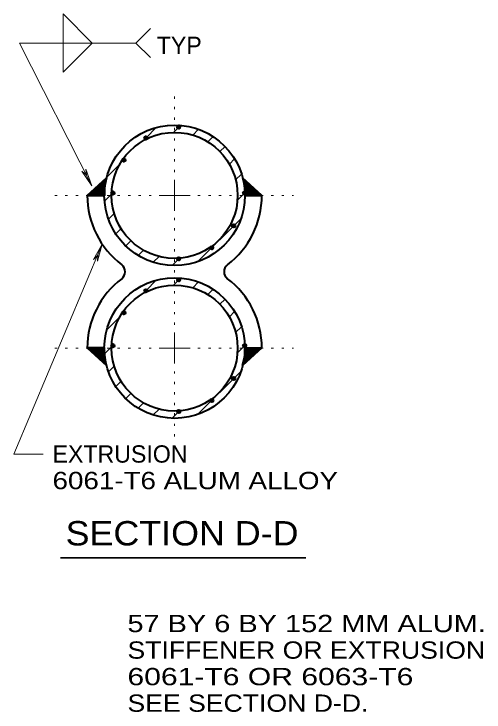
# Model space of a CAD drawing. Extents: x 312583 to 312854, y 144419 to 144597.
# Drawn here: x 312758.58 to 312779.22, y 144486.6 to 144517.27 of the extents above; entities that cross this region are included whole.
import ezdxf
from ezdxf.enums import TextEntityAlignment as Align

# ---------------------------------------------------------------- set-up
doc = ezdxf.new("R2010")
doc.units = 0
doc.header["$LTSCALE"] = 0.3
doc.header["$PDMODE"] = 32
doc.header["$PDSIZE"] = 0.15
doc.linetypes.add('DOTTED', pattern=[1.5, 0.3, -1.2])
doc.layers.add('1', color=7, linetype='Continuous', lineweight=40)

msp = doc.modelspace()

# ---------------------------------------------------------------- linework, layer by layer
at = {"layer": '1', "lineweight": 13}
for p, q in [((312761.9944, 144509.7243), (312758.8204, 144515.988)), ((312763.9341, 144515.988), (312764.5704, 144515.3516)), ((312765.5824, 144512.0626), (312765.8891, 144512.3693)), ((312764.3788, 144511.825), (312764.8234, 144512.2773)), ((312766.4258, 144511.9476), (312766.6788, 144512.2006)), ((312767.0928, 144511.6486), (312767.3228, 144511.8786)), ((312768.0358, 144510.6673), (312768.2658, 144510.8973)), ((312762.6538, 144510.1), (312763.2134, 144510.6596)), ((312761.5574, 144510.3683), (312761.7568, 144510.192)), ((312761.9944, 144509.7243), (312761.5574, 144510.3683)), ((312761.7261, 144510.4526), (312761.7568, 144510.192)), ((312761.9944, 144509.7243), (312761.7261, 144510.4526)), ((312768.3118, 144509.9773), (312768.5724, 144510.2303)), ((312765.6284, 144509.295), (312765.6284, 144509.9773)), ((312762.5541, 144509.042), (312762.8608, 144509.3486)), ((312765.6284, 144509.295), (312764.9461, 144509.295)), ((312765.6284, 144509.295), (312766.3108, 144509.295)), ((312765.6284, 144509.295), (312765.6284, 144508.6126)), ((312768.3884, 144509.088), (312768.7104, 144509.41)), ((312762.7304, 144508.2523), (312762.9758, 144508.4976)), ((312766.6558, 144506.3893), (312768.5418, 144508.2676)), ((312763.0524, 144507.6083), (312763.2824, 144507.8383)), ((312758.5751, 144497.9253), (312762.4544, 144507.1483)), ((312762.4544, 144507.1483), (312762.0711, 144506.4736)), ((312762.4544, 144507.1483), (312762.2474, 144506.4046)), ((312764.0338, 144506.6576), (312764.2638, 144506.8876)), ((312762.0711, 144506.4736), (312762.2551, 144506.6653)), ((312762.2474, 144506.4046), (312762.2551, 144506.6653)), ((312764.6931, 144506.3586), (312764.9538, 144506.6116)), ((312765.5211, 144506.213), (312765.8431, 144506.535)), ((312765.5824, 144505.3543), (312765.8891, 144505.661)), ((312764.3788, 144505.1166), (312764.8234, 144505.569)), ((312766.4258, 144505.2393), (312766.6788, 144505.4923)), ((312767.0928, 144504.9403), (312767.3228, 144505.1703)), ((312768.0358, 144503.959), (312768.2658, 144504.189)), ((312762.6538, 144503.3916), (312763.2134, 144503.9513)), ((312768.3118, 144503.269), (312768.5724, 144503.522)), ((312765.6284, 144502.5866), (312765.6284, 144503.269)), ((312762.5541, 144502.3336), (312762.8608, 144502.6403)), ((312765.6284, 144502.5866), (312764.9461, 144502.5866)), ((312765.6284, 144502.5866), (312766.3108, 144502.5866)), ((312765.6284, 144502.5866), (312765.6284, 144501.9043)), ((312768.3884, 144502.3796), (312768.7104, 144502.7016)), ((312762.7304, 144501.544), (312762.9758, 144501.7893)), ((312766.6558, 144499.681), (312768.5418, 144501.5593)), ((312763.0524, 144500.9), (312763.2824, 144501.13)), ((312764.0338, 144499.9493), (312764.2638, 144500.1793)), ((312764.6931, 144499.6503), (312764.9538, 144499.9033)), ((312765.5211, 144499.5046), (312765.8431, 144499.8266)), ((312758.5751, 144497.9253), (312759.8554, 144497.9253))]:
    msp.add_line(p, q, dxfattribs=at)
at = {"layer": '1', "linetype": 'DOTTED', "lineweight": 13}
for p, q in [((312765.6284, 144510.3223), (312765.6284, 144514.0023)), ((312764.6088, 144509.295), (312760.2311, 144509.295)), ((312766.6558, 144509.295), (312770.8571, 144509.295)), ((312765.6284, 144503.614), (312765.6284, 144508.375)), ((312764.6088, 144502.5866), (312760.2311, 144502.5866)), ((312766.6558, 144502.5866), (312770.8571, 144502.5866)), ((312765.6284, 144501.567), (312765.6284, 144498.5003))]:
    msp.add_line(p, q, dxfattribs=at)
at = {"layer": '1', "lineweight": 53}
for p, q in [((312762.5848, 144509.8316), (312762.4928, 144509.9313)), ((312762.6001, 144509.9006), (312762.5388, 144509.9696)), ((312762.6154, 144509.9696), (312762.5771, 144510.008)), ((312762.6384, 144510.0386), (312762.6231, 144510.0463)), ((312768.6261, 144510.0386), (312768.6414, 144510.0463)), ((312768.6414, 144509.9696), (312768.6798, 144510.008)), ((312768.6568, 144509.9006), (312768.7258, 144509.9696)), ((312768.6721, 144509.8316), (312768.7718, 144509.9313)), ((312762.4544, 144509.295), (312762.1478, 144509.6093)), ((312762.5464, 144509.3793), (312762.2321, 144509.6936)), ((312762.5464, 144509.4636), (312762.2704, 144509.732)), ((312762.5464, 144509.5403), (312762.3164, 144509.7703)), ((312762.5464, 144509.6246), (312762.3624, 144509.8086)), ((312762.5541, 144509.7013), (312762.4008, 144509.847)), ((312762.5694, 144509.7626), (312762.4468, 144509.893)), ((312768.6874, 144509.7626), (312768.8178, 144509.893)), ((312768.7028, 144509.7013), (312768.8561, 144509.847)), ((312768.7181, 144509.6246), (312768.9021, 144509.8086)), ((312768.7181, 144509.5403), (312768.9481, 144509.7703)), ((312768.7181, 144509.4636), (312768.9864, 144509.732)), ((312768.7181, 144509.3793), (312769.0324, 144509.6936)), ((312768.8024, 144509.295), (312769.1168, 144509.6093)), ((312761.8794, 144509.295), (312761.8411, 144509.3333)), ((312761.9561, 144509.295), (312761.8794, 144509.3716)), ((312762.0404, 144509.295), (312761.9254, 144509.41)), ((312762.1248, 144509.3026), (312761.9714, 144509.456)), ((312762.2091, 144509.295), (312762.0098, 144509.4943)), ((312762.2934, 144509.295), (312762.0558, 144509.5326)), ((312762.3778, 144509.295), (312762.1018, 144509.571)), ((312768.8868, 144509.295), (312769.1628, 144509.571)), ((312768.9711, 144509.295), (312769.2088, 144509.5326)), ((312769.0554, 144509.295), (312769.2471, 144509.4943)), ((312769.1398, 144509.3026), (312769.2931, 144509.456)), ((312769.2164, 144509.295), (312769.3391, 144509.41)), ((312769.3008, 144509.295), (312769.3774, 144509.3716)), ((312769.3851, 144509.295), (312769.4234, 144509.3333)), ((312761.8794, 144502.5943), (312761.8411, 144502.556)), ((312761.9561, 144502.5943), (312761.8794, 144502.5176)), ((312762.0404, 144502.5943), (312761.9254, 144502.4793)), ((312762.1248, 144502.5866), (312761.9714, 144502.4333)), ((312762.2091, 144502.5943), (312762.0098, 144502.395)), ((312762.2934, 144502.5943), (312762.0558, 144502.3566)), ((312762.3778, 144502.5943), (312762.1018, 144502.3183)), ((312762.4544, 144502.5943), (312762.1478, 144502.28)), ((312768.8024, 144502.5943), (312769.1168, 144502.28)), ((312768.8868, 144502.5943), (312769.1628, 144502.3183)), ((312768.9711, 144502.5943), (312769.2088, 144502.3566)), ((312769.0554, 144502.5943), (312769.2471, 144502.395)), ((312769.1398, 144502.5866), (312769.2931, 144502.4333)), ((312769.2164, 144502.5943), (312769.3391, 144502.4793)), ((312769.3008, 144502.5943), (312769.3774, 144502.5176)), ((312769.3851, 144502.5943), (312769.4234, 144502.556)), ((312762.5464, 144502.51), (312762.2321, 144502.1956)), ((312762.5464, 144502.4256), (312762.2704, 144502.1573)), ((312762.5464, 144502.349), (312762.3164, 144502.119)), ((312762.5464, 144502.2646), (312762.3624, 144502.0806)), ((312768.7181, 144502.51), (312769.0324, 144502.1956)), ((312768.7181, 144502.4256), (312768.9864, 144502.1573)), ((312768.7181, 144502.349), (312768.9481, 144502.119)), ((312768.7181, 144502.2646), (312768.9021, 144502.0806)), ((312762.5541, 144502.188), (312762.4008, 144502.0423)), ((312762.5694, 144502.1266), (312762.4468, 144501.9963)), ((312762.5848, 144502.0576), (312762.4928, 144501.958)), ((312762.6001, 144501.9886), (312762.5388, 144501.9196)), ((312768.6568, 144501.9886), (312768.7258, 144501.9196)), ((312768.6721, 144502.0576), (312768.7718, 144501.958)), ((312768.6874, 144502.1266), (312768.8178, 144501.9963)), ((312768.7028, 144502.188), (312768.8561, 144502.0423)), ((312762.6154, 144501.9196), (312762.5771, 144501.8813)), ((312762.6384, 144501.8506), (312762.6231, 144501.843)), ((312768.6261, 144501.8506), (312768.6414, 144501.843)), ((312768.6414, 144501.9196), (312768.6798, 144501.8813))]:
    msp.add_line(p, q, dxfattribs=at)
at = {"layer": '1'}
for p, q in [((312769.4618, 144509.295), (312768.6184, 144510.0616)), ((312761.7951, 144509.295), (312762.5464, 144509.295)), ((312769.4618, 144509.295), (312768.7181, 144509.295)), ((312762.5464, 144502.5866), (312761.7951, 144502.5866)), ((312769.4618, 144502.5866), (312768.7181, 144502.5866))]:
    msp.add_line(p, q, dxfattribs=at)
at = {"layer": '1', "lineweight": 35}
msp.add_line((312760.6241, 144493.379), (312771.3964, 144493.379), dxfattribs=at)
at = {"layer": '1', "lineweight": 13}
for points in [[(312762.0174, 144515.988), (312760.7371, 144517.2683), (312760.7371, 144515.988)], [(312758.8204, 144515.988), (312763.9341, 144515.988), (312764.5704, 144516.6243)], [(312762.0174, 144515.988), (312760.7371, 144514.7076), (312760.7371, 144515.988)], [(312767.6218, 144511.2193), (312767.8518, 144511.4416), (312767.8518, 144511.4416)], [(312763.4894, 144507.0793), (312763.4894, 144507.0793), (312763.7118, 144507.3016)], [(312767.6218, 144504.511), (312767.8518, 144504.7333), (312767.8518, 144504.7333)], [(312763.4894, 144500.371), (312763.4894, 144500.371), (312763.7118, 144500.5933)]]:
    msp.add_lwpolyline(points, dxfattribs=at)
at = {"layer": '1'}
for points in [[(312762.6384, 144510.0616), (312762.5464, 144509.663), (312762.5464, 144509.295), (312761.7951, 144509.295)], [(312768.6184, 144510.0616), (312768.7104, 144509.663), (312768.7181, 144509.295), (312769.4618, 144509.295)], [(312762.6384, 144501.8276), (312762.5464, 144502.2263), (312762.5464, 144502.5943), (312761.7951, 144502.5943)], [(312768.6184, 144501.8276), (312768.7104, 144502.2263), (312768.7181, 144502.5943), (312769.4618, 144502.5943)]]:
    msp.add_lwpolyline(points, close=True, dxfattribs=at)
at = {"layer": '1', "lineweight": 53}
for points in [[(312762.5464, 144509.295), (312762.5388, 144509.295), (312762.1861, 144509.6476)], [(312768.7181, 144509.295), (312768.7181, 144509.295), (312769.0708, 144509.6476)], [(312762.5464, 144502.5943), (312762.5388, 144502.5943), (312762.1861, 144502.2416)], [(312768.7181, 144502.5943), (312768.7181, 144502.5943), (312769.0708, 144502.2416)]]:
    msp.add_lwpolyline(points, dxfattribs=at)
at = {"layer": '1'}
for centre, radius in [((312765.631, 144509.2975), 3.0871), ((312765.631, 144509.2975), 2.7685), ((312765.631, 144502.5892), 3.0871), ((312765.631, 144502.5892), 2.7685)]:
    msp.add_circle(centre, radius, dxfattribs=at)
for centre, radius, start, end in [((312765.631, 144509.2975), 3.8333, 180, 232.69821), ((312765.631, 144509.2975), 3.8333, 307.30179, 0), ((312763.0756, 144505.9434), 0.3833, 307.30179, 52.69821), ((312768.1863, 144505.9434), 0.3833, 127.30179, 232.69821), ((312765.631, 144502.5892), 3.8333, 127.30179, 180), ((312765.631, 144502.5892), 3.8333, 0, 52.69821)]:
    msp.add_arc(centre, radius, start, end, dxfattribs=at)
for p in [(312765.8124, 144512.3003), (312764.3711, 144511.8173), (312763.4051, 144510.8513), (312762.9221, 144509.4023), (312768.7104, 144509.4023), (312768.2274, 144507.961), (312767.2614, 144506.995), (312765.8124, 144506.512), (312765.8124, 144505.592), (312764.3711, 144505.109), (312763.4051, 144504.143), (312762.9221, 144502.694), (312768.7104, 144502.694), (312768.2274, 144501.2526), (312767.2614, 144500.2866), (312765.8124, 144499.8036)]:
    msp.add_point(p, dxfattribs=at)

# ---------------------------------------------------------------- texts
for s, p in [('TYP', (312764.8477, 144515.5085)), ('EXTRUSION', (312760.2694, 144497.5563))]:
    msp.add_text(s, height=0.76, dxfattribs=at).set_placement(p)
for s, width, p in [('6061-T6 ALUM ALLOY', 1.2, (312760.2694, 144496.39)), ('57 BY 6 BY 152 MM ALUM.', 1.25, (312763.5603, 144490.1082)), ('STIFFENER OR EXTRUSION ALLOY', 1.15, (312763.5603, 144488.9419)), ('6061-T6 OR 6063-T6', 1.3, (312763.5603, 144487.7756)), ('SEE SECTION D-D.', 1.15, (312763.5603, 144486.6093))]:
    msp.add_text(s, height=0.76, dxfattribs=dict(at, width=width)).set_placement(p)
at = {"layer": '1', "width": 1.1}
msp.add_text('SECTION D-D', height=1.07, dxfattribs=at).set_placement((312765.9591, 144493.9184), align=Align.CENTER)

doc.saveas('drawing.dxf')
